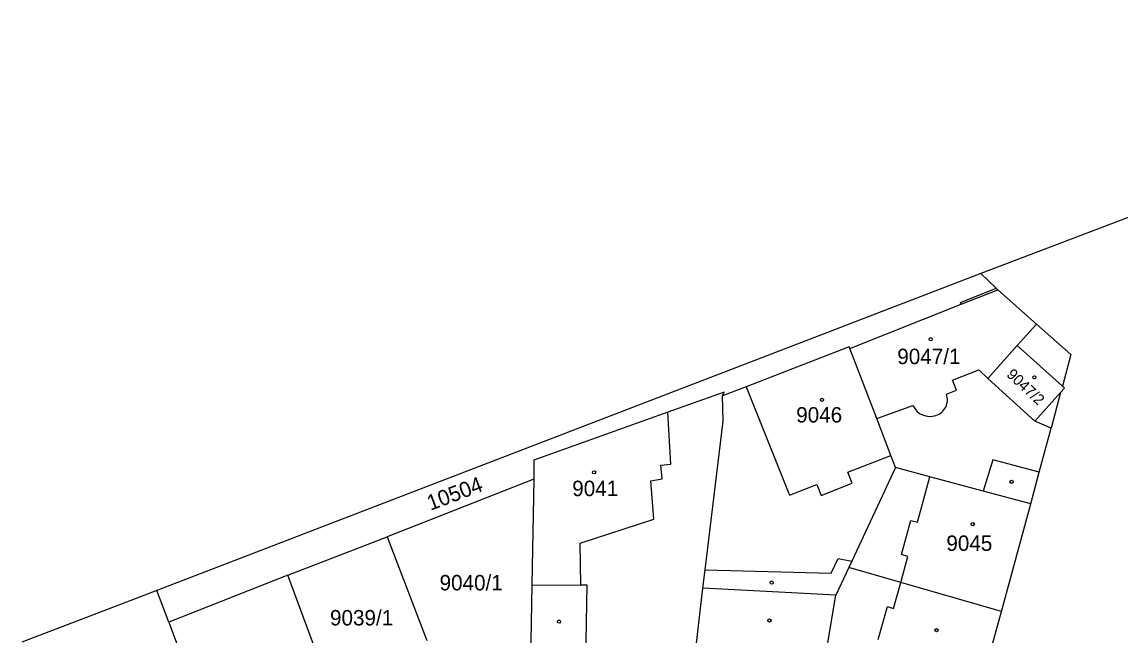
# Model space of a CAD drawing. Extents: x -825057 to -819383, y -1071633 to -1067888.
# Drawn here: x -824734.3 to -824613.4, y -1069973.4 to -1069905.9 of the extents above; entities that cross this region are included whole.
import ezdxf

# ---------------------------------------------------------------- set-up
doc = ezdxf.new("R2010")
doc.units = 0
for name, color, linetype in [('Vrstva 1', 7, 'Continuous'), ('Vrstva 13', 7, 'Continuous'), ('Vrstva 18', 7, 'Continuous'), ('Vrstva 19', 7, 'Continuous'), ('Vrstva 25', 7, 'Continuous'), ('Vrstva 4', 7, 'Continuous')]:
    doc.layers.add(name, color=color, linetype=linetype)

msp = doc.modelspace()

# ---------------------------------------------------------------- linework, layer by layer
at = {"layer": 'Vrstva 1'}
for p, q in [((-824627.01, -1069935.22), (-824628.7, -1069933.6)), ((-824630.87, -1069936.98), (-824626.84, -1069935.38)), ((-824626.84, -1069935.38), (-824627.01, -1069935.22)), ((-824626.84, -1069935.38), (-824622.57, -1069939.16)), ((-824643.14, -1069941.85), (-824630.87, -1069936.98)), ((-824624.7, -1069941.53), (-824622.57, -1069939.16)), ((-824622.57, -1069939.16), (-824618.8, -1069942.5)), ((-824643.21, -1069941.68), (-824654.56, -1069946.06)), ((-824643.14, -1069941.85), (-824643.21, -1069941.68)), ((-824640.17, -1069949.57), (-824643.14, -1069941.85)), ((-824627.96, -1069945.15), (-824624.7, -1069941.53)), ((-824618.8, -1069942.5), (-824619.74, -1069946)), ((-824654.56, -1069946.06), (-824657.15, -1069947.06)), ((-824622.77, -1069949.86), (-824627.96, -1069945.15)), ((-824619.74, -1069946), (-824619.5, -1069946.21)), ((-824656.97, -1069946.65), (-824663.17, -1069948.87)), ((-824657.15, -1069947.06), (-824656.97, -1069946.65)), ((-824657.06, -1069949.85), (-824657.15, -1069947.06)), ((-824619.93, -1069946.69), (-824620.98, -1069950.61)), ((-824619.5, -1069946.21), (-824619.93, -1069946.69)), ((-824663.17, -1069948.87), (-824677.92, -1069954.14)), ((-824638.61, -1069953.62), (-824640.17, -1069949.57)), ((-824659.05, -1069966.2), (-824657.06, -1069949.85)), ((-824620.98, -1069950.61), (-824622.77, -1069949.86)), ((-824622.29, -1069955.48), (-824620.98, -1069950.61)), ((-824677.92, -1069954.14), (-824677.92, -1069956.22)), ((-824638.09, -1069954.96), (-824638.61, -1069953.62)), ((-824638.09, -1069954.96), (-824642.93, -1069965.27)), ((-824634.34, -1069955.96), (-824638.09, -1069954.96)), ((-824623.22, -1069958.94), (-824622.29, -1069955.48)), ((-824677.92, -1069956.22), (-824694.05, -1069962.57)), ((-824677.92, -1069956.22), (-824678.14, -1069967.85)), ((-824628.46, -1069957.54), (-824634.34, -1069955.96)), ((-824623.22, -1069958.94), (-824628.46, -1069957.54)), ((-824626.42, -1069970.8), (-824623.22, -1069958.94)), ((-824704.98, -1069966.82), (-824694.05, -1069962.57)), ((-824694.05, -1069962.57), (-824689.71, -1069974.01)), ((-824642.93, -1069965.27), (-824643.25, -1069965.95)), ((-824659.3, -1069968.23), (-824659.05, -1069966.2)), ((-824643.25, -1069965.95), (-824644.67, -1069968.99)), ((-824637.51, -1069967.61), (-824643.25, -1069965.95)), ((-824704.98, -1069966.82), (-824718.11, -1069971.97)), ((-824700.78, -1069978.14), (-824704.98, -1069966.82)), ((-824626.42, -1069970.8), (-824637.51, -1069967.61)), ((-824718.11, -1069971.97), (-824719.41, -1069968.48)), ((-824678.14, -1069967.85), (-824678.3, -1069976.28)), ((-824660.05, -1069974.62), (-824659.3, -1069968.23)), ((-824644.67, -1069968.99), (-824659.3, -1069968.23)), ((-824645.72, -1069975.34), (-824644.67, -1069968.99)), ((-824629.59, -1069982.17), (-824626.42, -1069970.8)), ((-824718.11, -1069971.97), (-824710.7, -1069991.71))]:
    msp.add_line(p, q, dxfattribs=at)
at = {"layer": 'Vrstva 13'}
for p, q in [((-824556.05, -1069905.9), (-824628.7, -1069933.6)), ((-824628.7, -1069933.6), (-824719.41, -1069968.48)), ((-824719.41, -1069968.48), (-824722.28, -1069969.61)), ((-824722.28, -1069969.61), (-824734.26, -1069974.19))]:
    msp.add_line(p, q, dxfattribs=at)
at = {"layer": 'Vrstva 25'}
for centre in [(-824634.23, -1069940.83), (-824622.82, -1069945.02), (-824646.19, -1069947.5), (-824671.28, -1069955.48), (-824625.33, -1069956.53), (-824629.6, -1069961.19), (-824651.73, -1069967.62), (-824675.14, -1069971.91), (-824651.98, -1069971.79), (-824633.59, -1069972.86)]:
    msp.add_circle(centre, 0.175, dxfattribs=at)
at = {"layer": 'Vrstva 4'}
for p, q in [((-824630.95, -1069936.78), (-824627.01, -1069935.22)), ((-824630.87, -1069936.98), (-824630.95, -1069936.78)), ((-824619.74, -1069946), (-824624.7, -1069941.53)), ((-824631.82, -1069945.35), (-824628.93, -1069944.2)), ((-824628.93, -1069944.2), (-824627.96, -1069945.15)), ((-824654.56, -1069946.06), (-824649.76, -1069957.99)), ((-824631.39, -1069946.45), (-824631.82, -1069945.35)), ((-824632.5, -1069946.88), (-824631.39, -1069946.45)), ((-824622.77, -1069949.86), (-824619.93, -1069946.69)), ((-824640.17, -1069949.57), (-824636.18, -1069948.13)), ((-824662.83, -1069954.59), (-824663.17, -1069948.87)), ((-824643.35, -1069955.48), (-824638.61, -1069953.62)), ((-824627.4, -1069954.1), (-824628.46, -1069957.54)), ((-824622.29, -1069955.48), (-824627.4, -1069954.1)), ((-824663.93, -1069954.68), (-824662.83, -1069954.59)), ((-824663.79, -1069956.2), (-824663.93, -1069954.68)), ((-824642.88, -1069956.69), (-824643.35, -1069955.48)), ((-824665.05, -1069956.4), (-824663.79, -1069956.2)), ((-824664.7, -1069960.62), (-824665.05, -1069956.4)), ((-824649.76, -1069957.99), (-824646.75, -1069956.81)), ((-824646.75, -1069956.81), (-824646.28, -1069958.02)), ((-824646.28, -1069958.02), (-824642.88, -1069956.69)), ((-824635.7, -1069960.97), (-824634.34, -1069955.96)), ((-824672.81, -1069963.27), (-824664.7, -1069960.62)), ((-824637.45, -1069964.54), (-824636.42, -1069960.77)), ((-824636.42, -1069960.77), (-824635.7, -1069960.97)), ((-824672.75, -1069967.9), (-824672.81, -1069963.27)), ((-824645.18, -1069966.58), (-824644.43, -1069964.98)), ((-824644.43, -1069964.98), (-824642.93, -1069965.27)), ((-824637.51, -1069967.61), (-824636.73, -1069964.74)), ((-824636.73, -1069964.74), (-824637.45, -1069964.54)), ((-824659.05, -1069966.2), (-824645.18, -1069966.58)), ((-824638.32, -1069970.46), (-824637.51, -1069967.61)), ((-824678.14, -1069967.85), (-824672.75, -1069967.9)), ((-824672.05, -1069967.91), (-824672.75, -1069967.9)), ((-824672.19, -1069976.37), (-824672.05, -1069967.91)), ((-824640, -1069973.89), (-824638.97, -1069970.27)), ((-824638.97, -1069970.27), (-824638.32, -1069970.46))]:
    msp.add_line(p, q, dxfattribs=at)
for centre, radius, start, end in [((-824634.19, -1069947.495), 1.798, 287.46511, 19.99648), ((-824634.33, -1069947.298), 2.029, 204.19779, 289.56912)]:
    msp.add_arc(centre, radius, start, end, dxfattribs=at)

# ---------------------------------------------------------------- texts
at = {"layer": 'Vrstva 18'}
msp.add_text('10504', height=1.7, rotation=20.7, dxfattribs=at).set_placement((-824689.296, -1069959.722))
at = {"layer": 'Vrstva 19'}
for s, p in [('9047/1', (-824637.908, -1069943.57)), ('9046', (-824649.036, -1069950)), ('9041', (-824673.689, -1069958.1)), ('9045', (-824632.507, -1069964.13)), ('9040/1', (-824688.288, -1069968.48)), ('9039/1', (-824700.35, -1069972.34))]:
    msp.add_text(s, height=1.7, dxfattribs=at).set_placement(p)
msp.add_text('9047/2', height=1.2, rotation=316.8, dxfattribs=at).set_placement((-824625.966, -1069944.826))

doc.saveas('drawing.dxf')
